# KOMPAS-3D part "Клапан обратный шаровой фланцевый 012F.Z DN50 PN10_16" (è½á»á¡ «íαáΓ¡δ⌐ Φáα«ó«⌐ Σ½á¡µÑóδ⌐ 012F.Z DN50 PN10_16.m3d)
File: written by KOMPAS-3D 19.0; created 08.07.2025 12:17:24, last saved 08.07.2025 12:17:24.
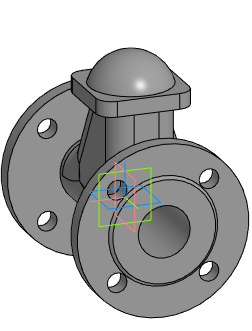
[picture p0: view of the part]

Document properties: Полное имя файла: E:\Dendor Работа Сачек\3D для проектировщиков\5.3 Тип 012F, 012F.Z Клапан обратный шаровой фланцевый\stp_Клапан обратный шаровой фланцевый 012F.Z PN10_16\Клапан обратный шаровой фланцевый 012F.Z DN50 PN10_16.m3d

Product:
- Part/product: Клапан обратный шаровой фланцевый 012F.Z DN50 PN10_16

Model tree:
1. Операция без истории:1  (labels: Клапан обратный шаровой фланцевый 012F.Z DN50 PN10_16)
